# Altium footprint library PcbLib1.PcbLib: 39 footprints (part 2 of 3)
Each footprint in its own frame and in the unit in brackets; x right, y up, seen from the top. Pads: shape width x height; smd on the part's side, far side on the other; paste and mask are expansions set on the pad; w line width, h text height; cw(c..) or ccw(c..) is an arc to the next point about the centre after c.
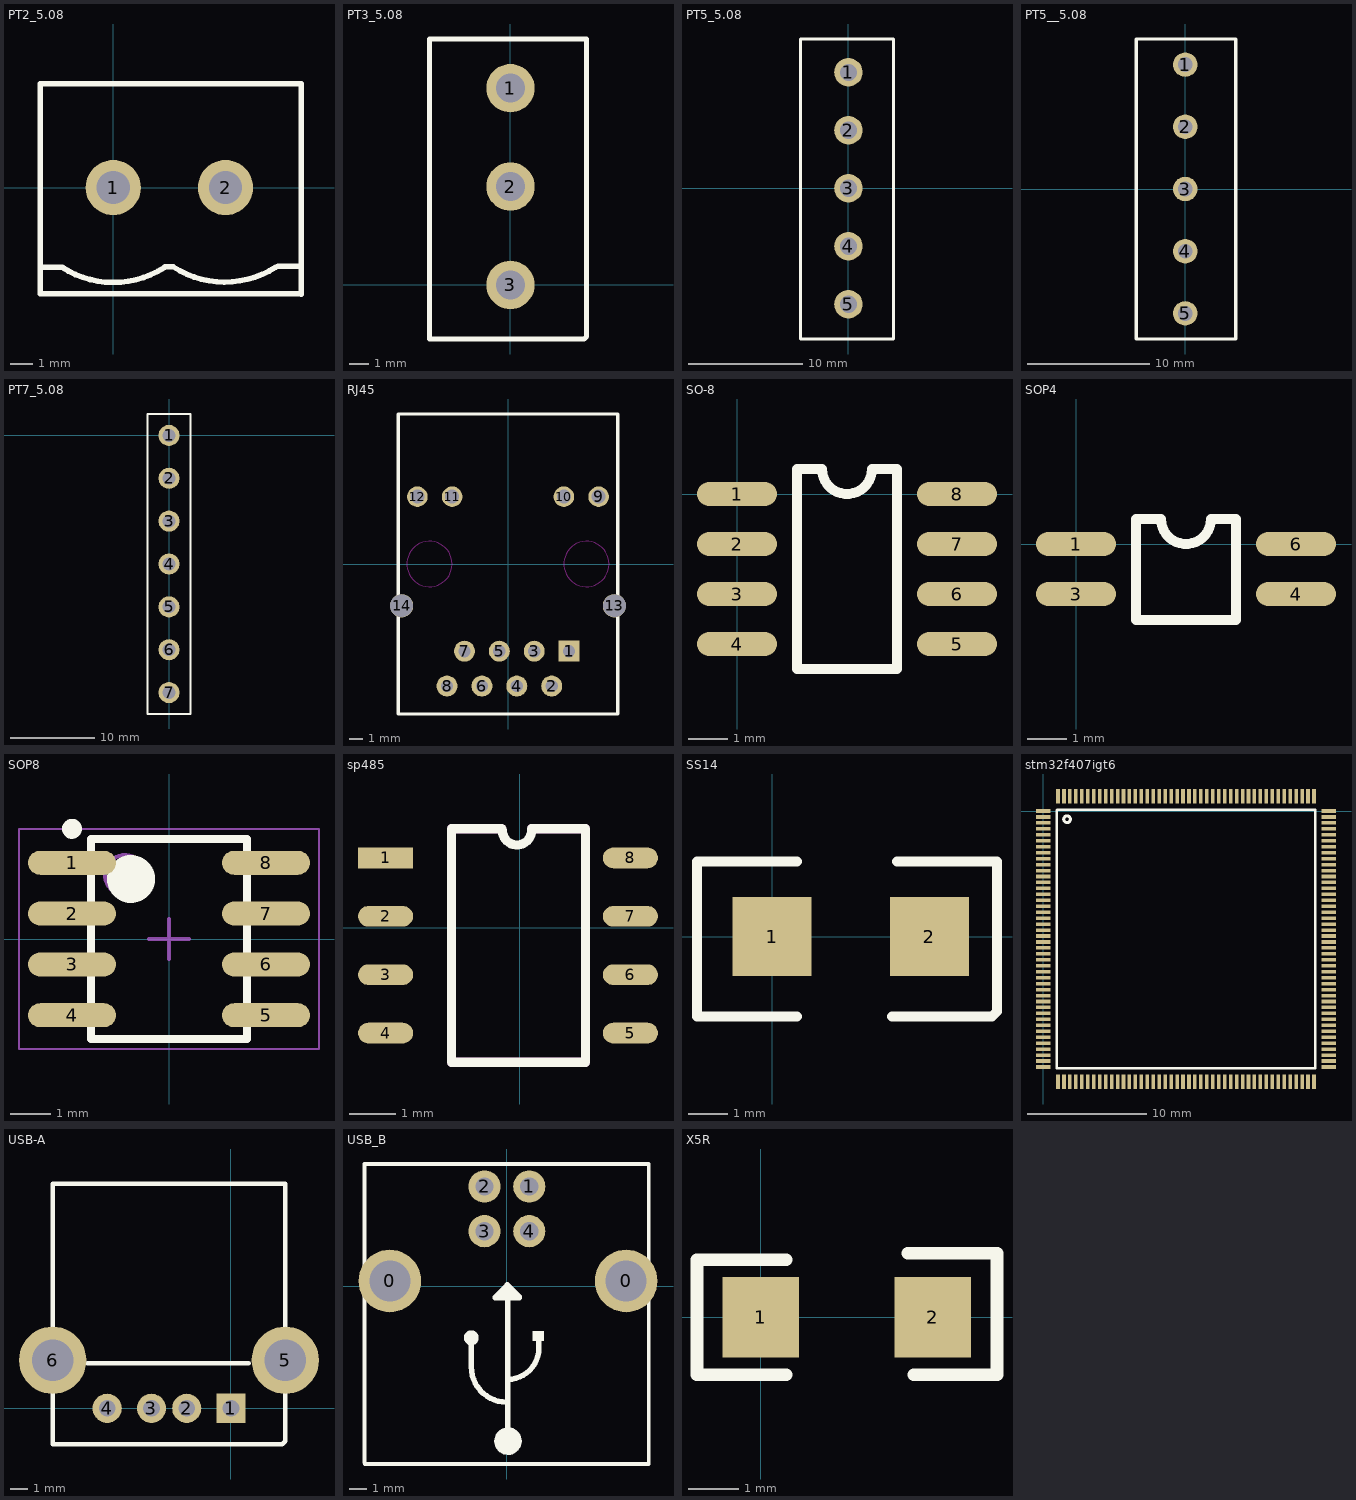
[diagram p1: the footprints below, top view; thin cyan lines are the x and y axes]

## PT2_5.08 [mm]
pads (2):
  round 2.5 hole 1.5: 1(0,0) 2(5.08,0)
Top Overlay:
  lines w0.254: -3.3,-3.596 -2.332,-3.596 ccw(c0.001,-0.024) 2.312,-3.61 ; -3.3,-0.3 -3.3,4.7 -0.2,4.7 ; -3.3,1.2 -3.3,0 -3.3,-2.7 -3.3,-4.8 0,-4.8 8.483,-4.8 8.509,-4.826 8.509,-1.111 8.509,4.7 -0.1,4.7 ; 2.34,-3.582 2.711,-3.582 ccw(c5.044,-0.01) 7.355,-3.596 ; 7.456,-3.556 8.382,-3.556

## PT3_5.08 [mm]
pads (3):
  round 2.5 hole 1.5: 1(0,10.16) 2(0,5.08) 3(0,0)
Top Overlay:
  lines w0.254: -4.191,-2.794 -4.191,12.7 3.937,12.7 3.937,-2.667 3.81,-2.794 -4.191,-2.794

## PT5_5.08 [mm]
pads (5):
  round 2.5 hole 1.5: 1(0,10.16) 2(0,5.08) 3(0,0) 4(0,-5.08) 5(0,-10.16)
Top Overlay:
  lines w0.254: -4.191,-13.208 3.937,-13.208 3.937,13.081 -4.191,13.081 -4.191,-13.208

## PT5__5.08 [mm]
pads (5):
  round 2 hole 1.2: 1(0,10.16) 2(0,5.08) 3(0,0) 4(0,-5.08) 5(0,-10.16)
Top Overlay:
  lines w0.254: 4,-12.25 -4,-12.25 -4,12.25 4,12.25 ; 4.128,-12.25 4.128,12.25

## PT7_5.08 [mm]
pads (7):
  round 2.5 hole 1.5: 1(0,0) 2(0,-5.08) 4(0,-15.24) 5(0,-20.32) 6(0,-25.4) 7(0,-30.48)
  round 2.5 hole 1.5 paste+0: 3(0,-10.16)
Top Overlay:
  lines w0.254: -2.54,-33.02 -2.54,2.54 2.54,2.54 2.54,-33.02 -2.54,-33.02

## RJ45 [mm]
height 3.8
pads (14):
  rect 1.524x1.524 hole 0.889: 1(4.45,-6.35)
  round 1.524 hole 0.889: 2(3.18,-8.89) 3(1.91,-6.35) 4(0.64,-8.89) 5(-0.63,-6.35) 6(-1.9,-8.89) 7(-3.17,-6.35) 8(-4.44,-8.89)
  round 1.5 hole 1.02: 9(6.6,4.9) 10(4.064,4.9) 11(-4.064,4.9) 12(-6.6,4.9)
  round 1.7 hole 1.65: 13(7.75,-3.048) 14(-7.75,-3.048)
Top Overlay:
  lines w0.254: -8,-10.922 0,-10.922 8,-10.922 8,10.922 0,10.922 -8,10.922 -8,-10.922
Keep-Out Layer:
  circle w0.051: c-5.714,0 r1.65
  circle w0.051: c5.716,0 r1.65

## SO-8 [mil]
pads (8):
  oval 80x24 smd: 1(0,0) 2(0,-50) 3(0,-100) 4(0,-150) 5(220,-150) 6(220,-100) 7(220,-50) 8(220,0)
Top Overlay:
  lines w10: 60,-175 60,25 85,25 ccw(c110,25) 135,25 160,25 160,-175 60,-175
3D body: height 63.6, standoff 0.6, extent -10.91,-172 224.91,20.91

## SOP4 [mil]
pads (4):
  oval 80x24 smd: 1(0,0) 3(0,-50) 4(220,-50) 6(220,0)
Top Overlay:
  lines w10: 60,-76 160,-76 160,25 135,25 cw(c110,25) 85,25 60,25 60,-76

## SOP8 [mm] "SOP, 8-Leads, Body 4.90x3.90mm, Pitch 1.27mm, IPC Medium Density"
height 3.8
pads (8):
  oval 2.2x0.6 smd: 1(-2.425,1.905) 2(-2.425,0.635) 3(-2.425,-0.635) 4(-2.425,-1.905) 5(2.425,-1.905) 6(2.425,-0.635) 7(2.425,0.635) 8(2.425,1.905)
Top Overlay:
  circle w0.6: c-0.95,1.5 r0.3
  circle w0.25: c-2.425,2.755 r0.125
  lines w0.2: -1.95,-2.5 1.95,-2.5 1.95,2.5 -1.95,2.5 -1.95,-2.5
Mechanical 13:
  circle w0.1: c-1.1,1.6 r0.5
  lines w0.1: -2,-2.5 2,-2.5 2,2.5 -2,2.5 -2,-2.5
Mechanical 15:
  lines w0.05: -3.75,-2.75 3.75,-2.75 3.75,2.75 -3.75,2.75 -3.75,-2.75
  lines w0.1: -0.5,0 0.5,0 ; 0,-0.5 0,0.5
3D body: height 4, standoff 3.8, extent -2,-2.5 2,2.5

## sp485 [mm]
pads (8):
  rect 1.2x0.45 smd: 1(-2.921,1.524)
  oval 1.2x0.45 smd: 2(-2.921,0.254) 3(-2.921,-1.016) 4(-2.921,-2.286) 5(2.404,-2.286) 6(2.404,-1.016) 7(2.404,0.254) 8(2.404,1.524)
Top Overlay:
  lines w0.2: -0.381,2.124 ccw(c-0.064,2.124) 0.254,2.124
Top Overlay keep-out:
  lines w0.2: -0.396,2.159 -1.486,2.159 -1.486,-2.921 1.429,-2.921 1.429,2.159 0.254,2.159

## SS14 [mm]
pads (2):
  rect 2x2 smd: 1(0,0) 2(4,0)
Top Overlay:
  lines w0.254: 0.635,-2.032 -1.905,-2.032 -1.905,1.905 0.635,1.905 ; 3.048,-2.032 5.588,-2.032 5.715,-1.905 5.715,1.905 3.175,1.905

## stm32f407igt6 [mm]
pads (176):
  rect 1.2x0.3 smd: 1(0,0) 2(0,-0.5) 3(0,-1) 4(0,-1.5) 5(0,-2) 6(0,-2.5) 7(0,-3) 8(0,-3.5) 9(0,-4) 10(0,-4.5) 11(0,-5) 12(0,-5.5) 13(0,-6) 14(0,-6.5) 15(0,-7) 16(0,-7.5) 17(0,-8) 18(0,-8.5) 19(0,-9) 20(0,-9.5) 21(0,-10) 22(0,-10.5) 23(0,-11) 24(0,-11.5) 25(0,-12) 26(0,-12.5) 27(0,-13) 28(0,-13.5) 29(0,-14) 30(0,-14.5) 31(0,-15) 32(0,-15.5) 33(0,-16) 34(0,-16.5) 35(0,-17) 36(0,-17.5) 37(0,-18) 38(0,-18.5) 39(0,-19) 40(0,-19.5) 41(0,-20) 42(0,-20.5) 43(0,-21) 44(0,-21.5) 89(24,-21.5) 90(24,-21) 91(24,-20.5) 92(24,-20) 93(24,-19.5) 94(24,-19) 95(24,-18.5) 96(24,-18) 97(24,-17.5) 98(24,-17) 99(24,-16.5) 100(24,-16) 101(24,-15.5) 102(24,-15) 103(24,-14.5) 104(24,-14) 105(24,-13.5) 106(24,-13) 107(24,-12.5) 108(24,-12) 109(24,-11.5) 110(24,-11) 111(24,-10.5) 112(24,-10) 113(24,-9.5) 114(24,-9) 115(24,-8.5) 116(24,-8) 117(24,-7.5) 118(24,-7) 119(24,-6.5) 120(24,-6) 121(24,-5.5) 122(24,-5) 123(24,-4.5) 124(24,-4) 125(24,-3.5) 126(24,-3) 127(24,-2.5) 128(24,-2) 129(24,-1.5) 130(24,-1) 131(24,-0.5) 132(24,0)
  rect 0.3x1.2 smd: 45(1.25,-22.75) 46(1.75,-22.75) 47(2.25,-22.75) 48(2.75,-22.75) 49(3.25,-22.75) 50(3.75,-22.75) 51(4.25,-22.75) 52(4.75,-22.75) 53(5.25,-22.75) 54(5.75,-22.75) 55(6.25,-22.75) 56(6.75,-22.75) 57(7.25,-22.75) 58(7.75,-22.75) 59(8.25,-22.75) 60(8.75,-22.75) 61(9.25,-22.75) 62(9.75,-22.75) 63(10.25,-22.75) 64(10.75,-22.75) 65(11.25,-22.75) 66(11.75,-22.75) 67(12.25,-22.75) 68(12.75,-22.75) 69(13.25,-22.75) 70(13.75,-22.75) 71(14.25,-22.75) 72(14.75,-22.75) 73(15.25,-22.75) 74(15.75,-22.75) 75(16.25,-22.75) 76(16.75,-22.75) 77(17.25,-22.75) 78(17.75,-22.75) 79(18.25,-22.75) 80(18.75,-22.75) 81(19.25,-22.75) 82(19.75,-22.75) 83(20.25,-22.75) 84(20.75,-22.75) 85(21.25,-22.75) 86(21.75,-22.75) 87(22.25,-22.75) 88(22.75,-22.75) 133(22.75,1.25) 134(22.25,1.25) 135(21.75,1.25) 136(21.25,1.25) 137(20.75,1.25) 138(20.25,1.25) 139(19.75,1.25) 140(19.25,1.25) 141(18.75,1.25) 142(18.25,1.25) 143(17.75,1.25) 144(17.25,1.25) 145(16.75,1.25) 146(16.25,1.25) 147(15.75,1.25) 148(15.25,1.25) 149(14.75,1.25) 150(14.25,1.25) 151(13.75,1.25) 152(13.25,1.25) 153(12.75,1.25) 154(12.25,1.25) 155(11.75,1.25) 156(11.25,1.25) 157(10.75,1.25) 158(10.25,1.25) 159(9.75,1.25) 160(9.25,1.25) 161(8.75,1.25) 162(8.25,1.25) 163(7.75,1.25) 164(7.25,1.25) 165(6.75,1.25) 166(6.25,1.25) 167(5.75,1.25) 168(5.25,1.25) 169(4.75,1.25) 170(4.25,1.25) 171(3.75,1.25) 172(3.25,1.25) 173(2.75,1.25) 174(2.25,1.25) 175(1.75,1.25) 176(1.25,1.25)
Top Overlay:
  circle w0.254: c2.005,-0.686 r0.281
  lines w0.2: 1.135,-21.615 1.135,0.068 1.182,0.115 22.865,0.115 22.865,-21.615 1.135,-21.615

## TJA1050 [mm]

## USB-A [mil]
pads (6):
  rect 65x65 hole 37: 1(0,0)
  round 65 hole 37: 2(-98.5,0) 3(-177,0) 4(-275.6,0)
  round 150 hole 93: 5(121,107) 6(-397,107)
Top Overlay:
  lines w10: -320,100 40,100 ; -397,-80 -397,107 -397,500 121,500 121,107 121,-73 114,-80 -397,-80
3D body: height 274.23, standoff -164.75, extent -449.02,-45 173.02,494.37

## USB_B [mm]
pads (6):
  round 3.5 hole 2.3: 0(-6.519,0.307) 0(6.681,0.307)
  round 1.8 hole 1.016: 1(1.27,5.588) 2(-1.23,5.588) 3(-1.23,3.088) 4(1.27,3.088)
Top Overlay:
  rectangle: -0.244,-9.118 0.456,-8.168
  rectangle: -2.069,-2.943 -1.869,-2.743
  rectangle: 1.456,-3.043 2.106,-2.493
  lines w0.203: -7.936,-9.844 -7.936,6.844 7.939,6.844 7.939,-9.92 ; -7.919,5.757 -7.919,-9.918 7.956,-9.918 7.956,5.757 ; -7.844,6.824 7.956,6.824
  lines w0.305: -1.969,-2.993 -1.969,-4.493 ccw(c0.006,-4.493) 0.006,-6.468 ; -1.755,-3.017 cw(c-1.969,-2.868) -1.719,-2.944 ; -0.644,-0.618 0.706,-0.618 0.456,-0.368 -0.369,-0.368 ; -0.619,-0.593 0.056,0.082 0.056,-8.393 ; -0.344,-8.318 ccw(c0.056,-8.568) -0.294,-8.252 ; -0.246,-8.119 ccw(c0.081,-8.643) -0.199,-8.093 ; 0.031,-0.168 0.031,0.107 0.706,-0.568 ; 0.056,-5.193 ccw(c0.056,-3.443) 1.806,-3.443 1.806,-3.093 ; 0.18,-8.391 ccw(c0.006,-8.518) 0.22,-8.491

## X5R [mm]
pads (2):
  rect 1.52x1.6 smd: 1(0,0) 2(3.42,0)
Top Overlay:
  lines w0.254: 0.508,-1.143 -1.27,-1.143 -1.27,1.143 -1.016,1.143 0.508,1.143 ; 2.921,1.27 4.699,1.27 4.699,-1.143 3.048,-1.143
